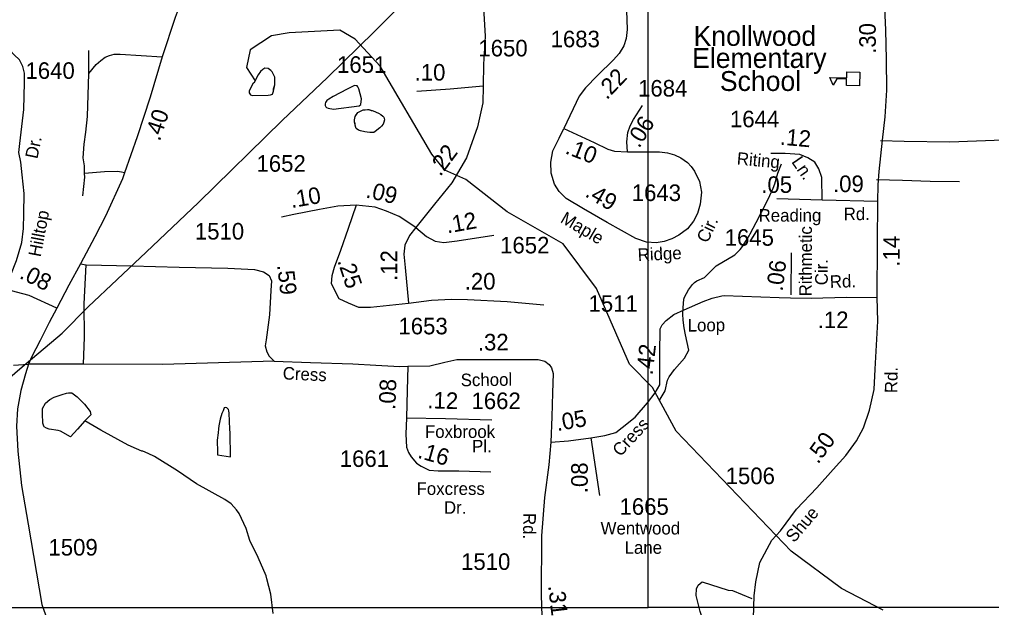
# Model space of a CAD drawing. Extents: x 1473865 to 1648260, y 639067 to 773536.
# Drawn here: x 1526062 to 1533398, y 678674 to 683113 of the extents above; entities that cross this region are included whole.
import ezdxf

# ---------------------------------------------------------------- set-up
doc = ezdxf.new("R2010")
doc.units = 0
for name, color, linetype in [('Exist Cultural Educational Facility High CELL', 7, 'Continuous'), ('Exist Cultural Educational Facility High Label', 7, 'Continuous'), ('Exist Hydrographic Misc Water Feature', 7, 'Continuous'), ('Exist Road Non-System Type 51', 7, 'Continuous'), ('Exist Road Secondary Mileage Hundredths English Label', 7, 'Continuous'), ('Exist Road Secondary Type 41 Attributed', 7, 'Continuous'), ('Exist Road Secondary Type 51 Attributed', 7, 'Continuous'), ('Exist Road Secondary Type 51 Label', 7, 'Continuous'), ('Exist Road Secondary Type 51 Number Label', 7, 'Continuous'), ('Exist Utilities Electrical Transmission Line', 7, 'Continuous'), ('Map Preparation Inset Cut Line', 7, 'Continuous')]:
    doc.layers.add(name, color=color, linetype=linetype)

msp = doc.modelspace()

# ---------------------------------------------------------------- linework, layer by layer
at = {"layer": 'Exist Cultural Educational Facility High CELL'}
msp.add_lwpolyline([(1532400.4, 682612), (1532302.6, 682615.3), (1532304.1, 682661.3), (1532229.1, 682663.8), (1532203.3, 682617.6), (1532176, 682675.2), (1532304.4, 682670.9), (1532306, 682716.9), (1532403.8, 682713.6)], close=True, dxfattribs=at)
at = {"layer": 'Exist Hydrographic Misc Water Feature'}
for points in [[(1532580.3, 678655), (1532266.3, 678818.9), (1531886.3, 679099.1), (1531017.3, 680006.1), (1530839.3, 680334.7), (1530666.2, 680512.1), (1530417.3, 681081.8), (1530164.3, 681418.4), (1529742.3, 681660), (1529430.3, 681905.9), (1529272.3, 681974.7), (1529174.3, 682094.9), (1528784.3, 682759.3), (1528596.2, 682963.3), (1528480.3, 683031.3), (1528097.2, 683012.8), (1527963.2, 682989.2), (1527803.3, 682884.1), (1527776.2, 682750.1), (1527841.2, 682650.3)], [(1527830.7, 682632.4), (1527824.7, 682630.9), (1527795.6, 682574.9), (1527795.5, 682559.3), (1527805.2, 682542.7), (1527817, 682538.3), (1527939.1, 682540.8), (1527955.2, 682542.9), (1527971.3, 682549.9), (1527979.8, 682571.9), (1527979.9, 682588.3), (1527988.6, 682620.2), (1527989.3, 682676), (1527967.9, 682716.6), (1527958.1, 682728.3), (1527938.3, 682742.6), (1527914.4, 682745.6), (1527898.3, 682735.3), (1527882, 682720), (1527863.7, 682694.1), (1527830.7, 682632.4)], [(1527830.7, 682632.4), (1527824.7, 682630.9), (1527795.6, 682574.9), (1527795.5, 682559.3), (1527805.2, 682542.7), (1527817, 682538.3), (1527939.1, 682540.8), (1527955.2, 682542.9), (1527971.3, 682549.9), (1527979.8, 682571.9), (1527988.6, 682620.2), (1527989.3, 682676), (1527967.9, 682716.6), (1527958.1, 682728.3), (1527938.3, 682742.6), (1527914.4, 682745.6), (1527898.3, 682735.3), (1527882, 682720), (1527863.7, 682694.1), (1527830.7, 682632.4)], [(1528642, 682514.3), (1528623, 682588.5), (1528615.3, 682604.3), (1528609.5, 682612.6), (1528591.4, 682612.9), (1528535.1, 682586.2), (1528430, 682531.7), (1528397.7, 682511.8), (1528381.5, 682499.8), (1528371.4, 682486.1), (1528369.1, 682476.3), (1528368.9, 682462.3), (1528372.8, 682454.1), (1528378.9, 682448.2), (1528392.7, 682442.2), (1528432.6, 682435.6), (1528625, 682460.5), (1528639.2, 682470), (1528642, 682514.3)], [(1528731.8, 682422.2), (1528771.4, 682405.8), (1528789.3, 682395.6), (1528803.1, 682383), (1528811, 682374.6), (1528814.9, 682364.7), (1528816.8, 682354.8), (1528812.3, 682336.8), (1528806, 682321.4), (1528793.8, 682306.9), (1528781.7, 682295.6), (1528771.8, 682287.6), (1528757.5, 682275.6), (1528745.2, 682266), (1528735, 682260.5), (1528719.2, 682258.3), (1528705, 682258.6), (1528685.2, 682260.7), (1528667.2, 682263.5), (1528635.4, 682271.5), (1528621.2, 682275.9), (1528611.4, 682284.3), (1528603.5, 682290.2), (1528597.9, 682305.9), (1528594.2, 682324), (1528590.4, 682340.5), (1528590.7, 682354.5), (1528592.8, 682368.4), (1528594.9, 682380.6), (1528603.1, 682392), (1528609.3, 682402.5), (1528615.4, 682409.8), (1528629.4, 682417.7), (1528645.6, 682425.6), (1528655.8, 682429.5), (1528671.8, 682431.6), (1528687.9, 682432.9), (1528697.9, 682432.7), (1528715.9, 682426.6), (1528731.8, 682422.2)], [(1528731.8, 682422.2), (1528771.4, 682405.8), (1528789.3, 682395.6), (1528803.1, 682383), (1528811, 682374.6), (1528814.9, 682364.7), (1528816.8, 682354.8), (1528812.3, 682336.8), (1528806, 682321.4), (1528793.8, 682306.9), (1528781.7, 682295.6), (1528757.5, 682275.6), (1528745.2, 682266), (1528735, 682260.5), (1528719.2, 682258.3), (1528705, 682258.6), (1528685.2, 682260.7), (1528667.2, 682263.5), (1528635.4, 682271.5), (1528621.2, 682275.9), (1528603.5, 682290.2), (1528597.9, 682305.9), (1528590.4, 682340.5), (1528590.7, 682354.5), (1528592.8, 682368.4), (1528594.9, 682380.6), (1528609.3, 682402.5), (1528615.4, 682409.8), (1528629.4, 682417.7), (1528645.6, 682425.6), (1528655.8, 682429.5), (1528671.8, 682431.6), (1528687.9, 682432.9), (1528697.9, 682432.7), (1528731.8, 682422.2)], [(1530890, 680233.5), (1530935.4, 680310.6), (1530952.5, 680390.6), (1530964.9, 680414.2), (1531004, 680470.1), (1531081.3, 680556.3), (1531114.3, 680616.4), (1531088, 680732.6), (1531076.8, 680784.5), (1531069.8, 680842.9), (1531068.4, 680888.9), (1531069.2, 680936.4), (1531076.2, 681001.1), (1531080.4, 681016.7), (1531109.5, 681071.9), (1531140, 681111.5), (1531156.4, 681127.6), (1531172.6, 681139.5), (1531230.9, 681166.3), (1531319.7, 681252.4), (1531459.7, 681337.3), (1531500.3, 681375.8), (1531518.8, 681400.1), (1531568, 681479.5), (1531576.4, 681494.9), (1531621.6, 681580.2), (1531698.1, 681731.3), (1531724.8, 681784.9), (1531749.7, 681840.2), (1531762.2, 681871.9), (1531783.6, 681951.9), (1531812.7, 682023.6)], [(1526555.9, 680083.8), (1526499, 680020.2), (1526447.9, 679961.3), (1526370.7, 680004.7), (1526354.8, 680010.7), (1526286.8, 680019.5), (1526265.1, 680028.2), (1526249.1, 680038.3), (1526245.3, 680044.2), (1526237.5, 680064.8), (1526234.6, 680136.3), (1526235.3, 680176.5), (1526258, 680216.2), (1526290.3, 680243.5), (1526322.7, 680260.9), (1526361, 680274.8), (1526385.1, 680282.6), (1526417.2, 680291.8), (1526433.1, 680295.6), (1526457.3, 680295.1), (1526496.7, 680264.7), (1526552, 680207.8), (1526595, 680152.8), (1526600.7, 680128.9), (1526555.9, 680083.8)], [(1527561.9, 679993.8), (1527555, 679938.2), (1527555.6, 679846.3), (1527557.3, 679826.5), (1527655.1, 679810.6), (1527651.9, 679992.8), (1527650.5, 680020.8), (1527644.3, 680140.7), (1527642.6, 680158.8), (1527638.7, 680168.7), (1527626.8, 680181.3), (1527615, 680183.1), (1527606.9, 680181.7), (1527598.5, 680159.7), (1527590.3, 680137.7), (1527577.5, 680096.1), (1527571, 680070), (1527566.9, 680046.2), (1527564.3, 680024.1), (1527561.9, 679993.8)], [(1527975.6, 678628.9), (1527957.9, 678774.5), (1527929.7, 678891.7), (1527924, 678913.1), (1527862.1, 679050.6), (1527800.3, 679179.8), (1527771.6, 679269.9), (1527719.3, 679385), (1527699.7, 679410.8), (1527658.6, 679456), (1527611.1, 679490.6), (1527396.8, 679608.1), (1527254.4, 679706.2), (1527079.9, 679813.1), (1527032.4, 679837.9), (1526992.5, 679854.3), (1526984.5, 679854.4), (1526944.8, 679871.7), (1526881.2, 679900), (1526674.8, 680011.7), (1526555.9, 680083.8)]]:
    msp.add_lwpolyline(points, dxfattribs=at)
at = {"layer": 'Exist Road Non-System Type 51'}
for p, q in [((1526586.1, 682705.6), (1526586.5, 682878.8)), ((1526546.5, 680512.1), (1526130.3, 680512))]:
    msp.add_line(p, q, dxfattribs=at)
for points in [[(1526586.1, 682705.6), (1526640.9, 682772.1), (1526676.4, 682803.7), (1526709.2, 682827.6), (1526742.2, 682839.8), (1526777.6, 682849.8), (1526822.4, 682849.8), (1527138.9, 682829.5)], [(1526554, 681949.8), (1526551.9, 682008.1), (1526542.9, 682068), (1526549.7, 682170.3), (1526562.5, 682262.7), (1526576, 682380.6), (1526586.1, 682705.6)], [(1532560.7, 682199.6), (1532738, 682194), (1533081.6, 682188.5), (1533685.6, 682210.7)], [(1526540.2, 681780.3), (1526555.1, 681921.4), (1526554, 681949.8)], [(1526853.4, 681955.4), (1526832.9, 681960.9), (1526801.8, 681965.2), (1526704, 681962.7), (1526554, 681949.8)], [(1533155.4, 681888.2), (1532933.4, 681890.5), (1532725.6, 681896.3), (1532529.5, 681902.9)], [(1526546.5, 680512.1), (1526552.2, 680715.8), (1526551, 680965.9), (1526564.6, 681261.6)], [(1527984.5, 680533.2), (1527143.7, 680509.6), (1526546.5, 680512.1)], [(1531263.3, 678224.2), (1531263.3, 678433.7), (1531237.8, 678519.8), (1531199.6, 678644.2), (1531167.7, 678765.4), (1531170.9, 678816.4), (1531184.8, 678842.9), (1531214, 678867.3), (1531410.5, 678806.3), (1531443.3, 678801.6), (1531587.5, 678741.8)]]:
    msp.add_lwpolyline(points, dxfattribs=at)
at = {"layer": 'Exist Road Secondary Type 41 Attributed'}
for points in [[(1526521.8, 681268.3), (1526564.6, 681261.6), (1526910.8, 681251.9)], [(1531363.3, 681027.9), (1531380, 681029), (1531794, 681015.2), (1531880.9, 681011.1)], [(1531880.9, 681011.1), (1532036.7, 681009.7), (1532302.8, 681016.6), (1532534.4, 681013.8)]]:
    msp.add_lwpolyline(points, dxfattribs=at)
at = {"layer": 'Exist Road Secondary Type 51 Attributed'}
for p, q in [((1532119.4, 681748.7), (1531776.1, 681758.4)), ((1532538.5, 681737.7), (1532119.4, 681748.7)), ((1526017.3, 680502.5), (1526130.3, 680512))]:
    msp.add_line(p, q, dxfattribs=at)
for points in [[(1532538.5, 681737.7), (1532542.7, 681864.5), (1532549.6, 681965.2), (1532575.8, 682202.3), (1532593.7, 682377.4), (1532606.1, 682578.7), (1532604.7, 682813.1), (1532600.6, 683030.9), (1532592.3, 683200.5), (1532590.9, 683382.5)], [(1530638, 683294.3), (1530641.6, 683179.8), (1530646.6, 683037.5), (1530640.2, 682970), (1530623.7, 682914.7), (1530587, 682855.8), (1530543.6, 682808.6), (1530424, 682689.1), (1530332.5, 682597.4), (1530286.2, 682533.3), (1530170.5, 682290.5)], [(1527281.6, 683248.1), (1527236.7, 683128.3), (1527138.9, 682829.5), (1527047.6, 682525.7), (1526949.7, 682226.6), (1526853.4, 681955.4), (1526838.4, 681910.5), (1526712.1, 681628.3), (1526632, 681472.5), (1526521.8, 681268.3)], [(1529561.2, 683243.4), (1529577.3, 682985.4), (1529570.8, 682895.1), (1529564.4, 682775.7), (1529561.2, 682608)], [(1525953.8, 681077.9), (1526040.9, 681294.4), (1526079.7, 681429.8), (1526092.7, 681534.5), (1526095, 681645.1), (1526097.4, 681799.2), (1526083.2, 681939.3), (1526071.5, 682034.6), (1526058.5, 682108.7), (1526065.6, 682175.8), (1526095, 682432.3), (1526100.9, 682637), (1526100.9, 682706.5), (1526087.9, 682758.2), (1526062.1, 682807.7), (1526023.2, 682846.5), (1525991.5, 682878.3), (1525921.7, 682908.8), (1525870.2, 682922.6), (1525731.6, 682938.3), (1525558.4, 682921.4)], [(1529561.2, 682608), (1529557.9, 682482.2), (1529519.3, 682301.6), (1529435.5, 682069.4), (1529325.5, 681880.1), (1529192.7, 681719.1), (1529053.6, 681541.4)], [(1529561.2, 682608), (1529313, 682585.4), (1529061.6, 682569.3)], [(1530649.5, 682113), (1530645.9, 682188.4), (1530651.7, 682258.8), (1530670.3, 682310.6), (1530696.9, 682357.3), (1530764.4, 682463.6)], [(1530649.5, 682113), (1530892.9, 682114.4), (1530951.1, 682106.6), (1531005.7, 682090.8), (1531053.8, 682067), (1531102.6, 682033.3), (1531130.6, 682001.7), (1531156.5, 681967.9), (1531194, 681890.8), (1531209.5, 681810), (1531199.6, 681719.4), (1531178.8, 681649), (1531149.3, 681590.1), (1531103.4, 681531.2), (1531038.8, 681483.9), (1530985.6, 681456.5), (1530928.1, 681437.8), (1530867.1, 681427.7), (1530793.1, 681432.8), (1530712.7, 681459.3), (1530498, 681580), (1530318.6, 681682.7), (1530187.1, 681760.3), (1530133.9, 681813.5), (1530100.2, 681870.2), (1530075, 681951.4), (1530071.4, 682035.4), (1530088, 682121.6), (1530133.9, 682216.5), (1530170.5, 682290.5)], [(1530170.5, 682290.5), (1530399.3, 682182.7), (1530501.7, 682133), (1530551.4, 682117.5), (1530649.5, 682113)], [(1532119.4, 681748.7), (1532118, 681919.7), (1532094.6, 681984.5), (1532064.3, 682035.5), (1532010.5, 682068.6), (1531950.6, 682093.1), (1531839.8, 682102), (1531731.1, 682099.8)], [(1532534.4, 681013.8), (1532537.2, 681427.5), (1532538.5, 681737.7)], [(1528602.4, 681711.4), (1528465.7, 681703.6), (1528327, 681678.2), (1528133.7, 681641.1), (1528039.9, 681621.5)], [(1528602.4, 681711.4), (1528541.9, 681535.5), (1528485.2, 681369.4), (1528436.4, 681240.5), (1528418, 681177.6), (1528414.6, 681120.1), (1528472.6, 681007.2), (1528543.2, 680972.6), (1528619.6, 680940.4), (1528712.1, 680940.4), (1528997.9, 680971.8)], [(1529053.6, 681541.4), (1528926.6, 681625.4), (1528830.9, 681664.5), (1528747, 681695.8), (1528602.4, 681711.4)], [(1529053.6, 681541.4), (1529005.7, 681481.7), (1528969.5, 681409.2), (1528963.5, 681340.8), (1528971.6, 681240.5), (1528997.9, 680971.8)], [(1529053.6, 681541.4), (1529132.4, 681475.6), (1529198.8, 681439.4), (1529265.1, 681429.3), (1529365.7, 681441.4), (1529641.2, 681485.7)], [(1531886.2, 681034.5), (1531887, 681351.6)], [(1526521.8, 681268.3), (1526434.8, 681107.7), (1526344.5, 680934.4)], [(1526910.8, 681251.9), (1527268.3, 681242), (1527634.2, 681235), (1527835.9, 681225.1), (1527904, 681207.9), (1527945.5, 681179.4), (1527964.7, 681140.9), (1527958.4, 681066.5), (1527947.7, 680883.1), (1527924.1, 680693.7), (1527914.9, 680648.6), (1527927.9, 680605), (1527947.5, 680572.4), (1527984.5, 680533.2), (1528258.5, 680522.3), (1528578.2, 680513.6), (1528750.1, 680503.5), (1528931.8, 680494.1), (1528991.7, 680494.7)], [(1526344.5, 680934.4), (1526134.9, 681029.4), (1525953.8, 681077.9)], [(1528997.9, 680971.8), (1529170.6, 680994.7), (1529321.4, 681000.8), (1529442.1, 680998.8), (1529741.6, 680984.9), (1530018.8, 680959.1)], [(1530373.2, 679955.5), (1530479.7, 679971.6), (1530562.2, 679995.7), (1530611, 680033.8), (1530707.6, 680112.1), (1530801.3, 680218.3), (1530859.2, 680294.1), (1530893.7, 680356.2), (1530893.7, 680593.3), (1530897.8, 680778.1), (1530913, 680808.4), (1530943.3, 680841.5), (1531000.2, 680884.6), (1531078.1, 680920.8), (1531220.5, 680983.5), (1531289.4, 681008.3), (1531363.3, 681027.9)], [(1531589.4, 678148.9), (1531587.1, 678362.5), (1531600.6, 678594), (1531605.1, 678762.7), (1531618.6, 678868.3), (1531648.3, 679013.3), (1531740, 679183.1), (1531803.7, 679252.8), (1531924.8, 679417.7), (1532079.4, 679578.7), (1532203.1, 679715.9), (1532297.5, 679821.5), (1532378.5, 679931.7), (1532432.4, 680030.6), (1532477.4, 680163.3), (1532512.4, 680319.2), (1532518.1, 680472), (1532538.3, 680834.7), (1532534.4, 681013.8)], [(1526344.5, 680934.4), (1526285.6, 680826.1), (1526217.4, 680690.8), (1526152.7, 680564.9), (1526130.3, 680512)], [(1528991.7, 680494.7), (1529158.6, 680498.7), (1529271.2, 680526.9), (1529363.7, 680545), (1529619.1, 680545), (1529977, 680545), (1530027.3, 680533), (1530059.6, 680509.2), (1530077.5, 680483), (1530089.9, 680441.7), (1530083.6, 680293.5), (1530079.6, 680112.4), (1530072.8, 679922.2)], [(1526130.3, 680512), (1526106.8, 680439), (1526071.5, 680311.9), (1526046.8, 680173.1), (1526039.7, 680043.6), (1526050.4, 679853.1), (1526077.7, 679596), (1526128.8, 679302.5), (1526231.2, 678696.5), (1526259.3, 678619.4), (1526294.3, 678488.6), (1526335.8, 678351.4), (1526402.7, 678211.1), (1526496.5, 678073.8), (1526546.5, 677964.9), (1526603.5, 677869.8), (1526937.6, 677224.9), (1527173.3, 676812.1), (1527275.2, 676628.6), (1527383.7, 676412.1), (1527585.6, 676023.6), (1527618.7, 675951.5)], [(1528991.7, 680494.7), (1528987.6, 680311.6), (1528983.6, 680106.4)], [(1528983.6, 680106.4), (1528977.6, 679983.7), (1528983.6, 679885.1), (1528997.7, 679844.8), (1529017.8, 679812.6), (1529058, 679764.3), (1529092.1, 679741.1), (1529152.5, 679712), (1529220.9, 679706), (1529377.8, 679706), (1529619.1, 679697.9)], [(1528983.6, 680106.4), (1529276.9, 680101.8), (1529627.1, 680090.3)], [(1530072.8, 679922.2), (1530204.2, 679931.3), (1530373.2, 679955.5)], [(1530373.2, 679955.5), (1530439.5, 679520.9)], [(1530072.8, 679922.2), (1530057.1, 679751.1), (1530024.3, 679504.5), (1530002.2, 679216.5), (1529997.7, 678767.2), (1530005.1, 678609.1), (1530032.2, 678505.3), (1530068, 678412.3), (1530132.6, 678317.5)]]:
    msp.add_lwpolyline(points, dxfattribs=at)
at = {"layer": 'Exist Utilities Electrical Transmission Line'}
msp.add_lwpolyline([(1523995.9, 678298.1), (1524324.1, 678686.3), (1524661, 679078.1), (1525004.1, 679482), (1525214.5, 679734.1), (1525277.7, 679803), (1525698.1, 680159.3), (1526063.7, 680476.7), (1526384.9, 680744), (1526581.4, 680943.3), (1527017.1, 681355.5), (1527413.7, 681732.3), (1528044.6, 682348.9), (1528386.4, 682674.8), (1528738.5, 683020.4), (1529088.6, 683369.9), (1529286.4, 683584.5), (1529759.7, 684112), (1530292.1, 684694.3), (1530813.9, 685256.9), (1531254.4, 685736.8), (1531515.5, 686026.1), (1531664.1, 686167.8)], dxfattribs=at)
at = {"layer": 'Map Preparation Inset Cut Line'}
msp.add_lwpolyline([(1530807.2, 678673.7), (1530807.2, 722115.9), (1605695.7, 722115.9), (1605695.7, 695030), (1593323.3, 695030), (1593323.3, 678673.7), (1530807.2, 678673.7)], dxfattribs=at)
msp.add_lwpolyline([(1530807.2, 690698.7), (1516075.6, 690698.7), (1516075.6, 678674.1), (1530807.2, 678674.1)], close=True, dxfattribs=at)

# ---------------------------------------------------------------- texts
at = {"layer": 'Exist Cultural Educational Facility High Label'}
for s, p in [('Knollwood', (1531148.8, 682913.5)), ('Elementary', (1531138.1, 682746.5)), ('School', (1531347.3, 682572.9))]:
    msp.add_text(s, height=150, rotation=0.00002, dxfattribs=at).set_placement(p)
at = {"layer": 'Exist Road Secondary Mileage Hundredths English Label'}
for s, rotation, p in [('.30', 90.51044, (1532525.1, 682853.5)), ('.22', 46.23032, (1530493.9, 682502.1)), ('.40', 71.88249, (1527120.5, 682188.4)), ('.06', 58.19084, (1530737.8, 682135.6)), ('.12', 354.96218, (1531797.3, 682167.9)), ('.22', 53.63211, (1529238, 681922.5)), ('.10', 338.69699, (1530173.1, 682103.7)), ('.09', 0.16793, (1532201.5, 681809.4)), ('.09', 346.99793, (1528669.7, 681770.2)), ('.05', 0.16786, (1531660.3, 681803.3)), ('.10', 10.01384, (1528115.4, 681688.3)), ('.49', 329.81757, (1530322.8, 681780.5)), ('.12', 10.27776, (1529291.8, 681497.3)), ('.14', 89.65986, (1532703.9, 681246.9)), ('.12', 90, (1528912.7, 681139.1)), ('.25', 288.4239, (1528459.6, 681291)), ('.06', 83.04212, (1531821.2, 681057.6)), ('.08', 333.56408, (1526054.7, 681163)), ('.59', 276.29297, (1528006.3, 681258.6)), ('.20', 0.17845, (1529422.4, 681073.7)), ('.12', 0.07876, (1532086.1, 680783.1)), ('.32', 0.61071, (1529521.7, 680613.5)), ('.42', 83.29411, (1530838.9, 680424.4)), ('.08', 87.8673, (1528898.1, 680165)), ('.12', 358.36431, (1529138.5, 680178.3)), ('.05', 9.97243, (1530120.5, 680005.2)), ('.50', 53.70898, (1532087.9, 679751.6)), ('.16', 344.06205, (1529060.5, 679806)), ('.08', 90, (1530350.3, 679537)), ('.31', 276.52639, (1530051.1, 678837.7))]:
    msp.add_text(s, height=125, rotation=rotation, dxfattribs=at).set_placement(p)
msp.add_text('.10', height=125, dxfattribs=at).set_placement((1529044.1, 682651.4))
at = {"layer": 'Exist Road Secondary Type 51 Label'}
for s, rotation, p in [('Dr.', 78.27616, (1526196.9, 682056.1)), ('Riting', 354.96218, (1531472.5, 682017.3)), ('Ln.', 304.50816, (1531884, 682037.9)), ('Hilltop', 79.3716, (1526222.2, 681315.8)), ('Maple', 329.63011, (1530137, 681585.4)), ('Reading', 0.16786, (1531639.8, 681586.3)), ('Rd.', 0.16793, (1532281.9, 681597.6)), ('Cir.', 64.64077, (1531253.3, 681418.9)), ('Rithmetic', 89.8589, (1532040.8, 681022.8)), ('Ridge', 2.67312, (1530729.3, 681288.7)), ('Cir.', 89.8589, (1532161.5, 681106.5)), ('Rd.', 1.48609, (1532178.2, 681086.6)), ('Loop', 0.73657, (1531104.9, 680756.7)), ('Cress', 357.43768, (1528047, 680396.2)), ('Rd.', 89.5038, (1532687, 680291.8)), ('School', 0.61071, (1529392.2, 680344.1)), ('Cress', 47.22526, (1530596.5, 679807.7)), ('Rd.', 269.47896, (1529864.1, 679388)), ('Shue', 49.51828, (1531907.5, 679158.5))]:
    msp.add_text(s, height=95, rotation=rotation, dxfattribs=at).set_placement(p)
for s, p in [('Foxbrook', (1529121.7, 679954.4)), ('Pl.', (1529477.4, 679844.7)), ('Foxcress', (1529058.5, 679524)), ('Dr.', (1529265.2, 679381.5)), ('Wentwood', (1530447.3, 679225.6)), ('Lane', (1530628.5, 679079.7))]:
    msp.add_text(s, height=95, dxfattribs=at).set_placement(p)
at = {"layer": 'Exist Road Secondary Type 51 Number Label'}
for s, p in [('1650', (1529525, 682833.7)), ('1683', (1530070.1, 682902.5)), ('1651', (1528458.3, 682709.7)), ('1640', (1526107.5, 682664.2)), ('1684', (1530730.1, 682530.7)), ('1644', (1531423.6, 682298.8)), ('1652', (1527850.8, 681963.4)), ('1643', (1530682.4, 681742.2)), ('1510', (1527385.7, 681451.7)), ('1645', (1531383.6, 681404.8)), ('1652', (1529689.1, 681346.8)), ('1511', (1530356.3, 680906.5)), ('1653', (1528921.9, 680736.1)), ('1662', (1529473.3, 680171.9)), ('1661', (1528479.2, 679735.3)), ('1506', (1531391.1, 679605.5)), ('1665', (1530590.3, 679374)), ('1509', (1526280.9, 679066.4)), ('1510', (1529394.6, 678958.2))]:
    msp.add_text(s, height=125, dxfattribs=at).set_placement(p)

doc.saveas('drawing.dxf')
